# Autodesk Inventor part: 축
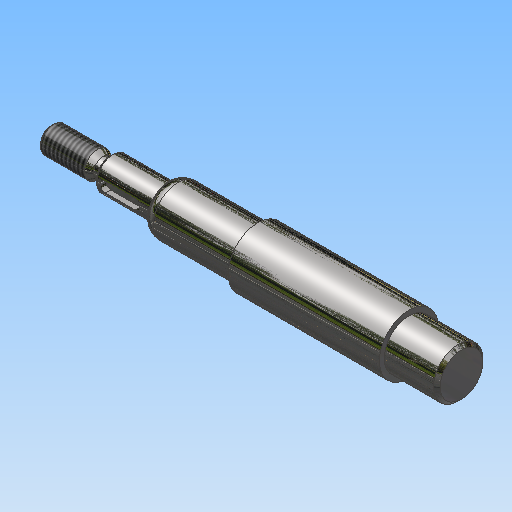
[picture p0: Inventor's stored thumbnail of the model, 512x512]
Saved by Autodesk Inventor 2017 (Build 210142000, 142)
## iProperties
Created: 2015-11
Part Number: 축
Material: 강철, 연강
Document SubType Name: Modeling
Designer: mduedu
Density: 1 g/cm^3
Appearance: 반광택
Author: mduedu
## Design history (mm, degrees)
sketch "스케치1"
  geometry: L1 (-86, 0)-(86, 0); L2 (-86, 0)-(-86, 4); L3 (-86, 4)-(-71.732, 4); L4 (-71.732, 4)-(-70, 3); L5 (-70, 3)-(-68, 3); L6 (-68, 3)-(-68, 5); L7 (-68, 5)-(-50, 5); L8 (-50, 5)-(-50, 6.55); L9 (-48.355, 7.5)-(-23, 7.5); L10 (-23, 7.5)-(-23, 9); L11 (0, 0)-(0, 9); L12 (86, 4)-(71.732, 4); L13 (71.732, 4)-(70, 3); L14 (70, 3)-(68, 3); L15 (68, 3)-(68, 5); L16 (68, 5)-(50, 5); L17 (23, 7.5)-(23, 9); L18 (86, 0)-(86, 4); L19 (-23, 9)-(23, 9); L20 (-50, 6.55)-(-48.355, 7.5); L21 (48.355, 7.5)-(23, 7.5); L22 (50, 6.55)-(48.355, 7.5); L23 (50, 5)-(50, 6.55); 1 further point
  constraints: 46 end point, 10 symmetric about line, 6 perpendicular, 5 parallel, 2 midpoint, 1 coincident, 1 horizontal
  dimensions: "d0" = 172 distance of L1.start L1.end (derived); "d1" = 8 diameter of L3 L1; "d2" = 30 deg angle of L4 L5; "d3" = 6 diameter of L5 L1; "d4" = 10 diameter of L7 L1; "d5" = 15 diameter of L9 L1; "d6" = 18 diameter of L19 L1; "d8" = 18 distance of L6.end L7.end; "d9" = 46 distance of L10.end L17.end; "d10" = 2 distance of L4.end L5.end; "d11" = 16 distance from line of L4.end L2; "d16" = 13.1 diameter of L8.end L1; "d17" = 30 deg angle of L20 L9; "d18" = 27 distance between parallel lines of L10 L8
revolve "회전1" sketch "스케치1" stored, may be unused: angle "d12" = 90 deg
chamfer "모따기1" distance "d13" = 1; stored, may be unused: second distance "d14" = 2, angle "d15" = 45 deg
fillet "모깎기1" dims "d19" = 4, "d20" = 0.5
node "작업 평면1"
sketch "스케치2" dims "d23" = 12
  geometry: L1 (-5.5, 1.5)-(3.5, 1.5); L2 (3.5, 1.5)-(3.5, -1.5); L3 (3.5, -1.5)-(-5.5, -1.5); L4 (-5.5, -1.5)-(-5.5, 1.5); L5 (-9, -4)-(-9, 4) reference; 3 further points
  constraints: 8 end point, 2 midpoint, 2 parallel, 2 vertical alignment, 1 horizontal, 1 perpendicular, 4 other
  dimensions: "d21" = 3 distance between parallel lines of L3 L1; "d24" = 2 dimension on L5
extrude "돌출1" cut sketch "스케치2" distance "d25" = 1.8; taper "d26" = 0 deg
feature "스레드1" dims "d27" = 10, "d28" = 0
feature "스레드2" dims "d29" = 10, "d30" = 0
chamfer "모따기2" distance "d31" = 1; stored, may be unused: second distance "d32" = 2, angle "d33" = 45 deg
node "작업 평면2"
sketch "스케치3"
  geometry: C1 r 7.5 at (0, 0) reference; 1 further point
extrude "돌출2" cut sketch "스케치3" stored distance "d36" = 10; taper "d37" = 0 deg
chamfer "모따기3" distance "d38" = 1; stored, may be unused: second distance "d39" = 2, angle "d40" = 45 deg
node "솔리드1"
mirror "대칭1"
node "절단 모서리 투영1"
other parameters: "d35" = 16
